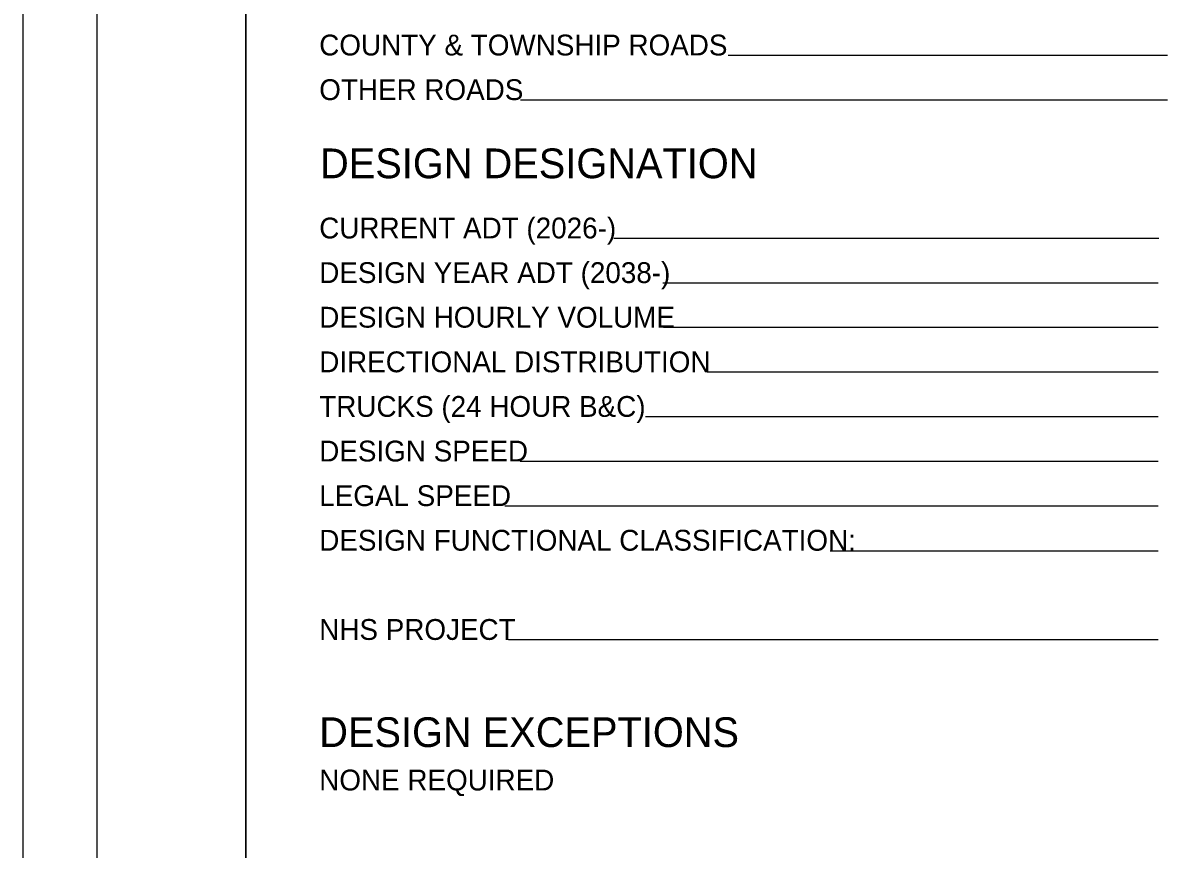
# Model space of a CAD drawing. Extents: x -107 to 120, y -81 to 213.
# Drawn here: x 3.89 to 11.53, y 7.13 to 12.69 of the extents above; entities that cross this region are included whole.
import ezdxf

# ---------------------------------------------------------------- set-up
doc = ezdxf.new("R2010")
doc.units = 0
for name, color, linetype in [('SH_Border', 7, 'Continuous'), ('SH_Cut_Line', 7, 'Continuous'), ('SH_Data', 7, 'Continuous'), ('SH_Text', 7, 'Continuous')]:
    doc.layers.add(name, color=color, linetype=linetype)

msp = doc.modelspace()

# ---------------------------------------------------------------- linework, layer by layer
at = {"layer": 'SH_Border'}
for points in [[(4.389, 23.0682), (5.389, 23.0682), (5.389, 2.0682), (4.389, 2.0682)], [(5.389, 23.0682), (37.389, 23.0682), (37.389, 2.0682), (5.389, 2.0682)]]:
    msp.add_lwpolyline(points, close=True, dxfattribs=at)
at = {"layer": 'SH_Cut_Line'}
msp.add_lwpolyline([(3.889, 1.5682), (37.889, 1.5682), (37.889, 23.5682), (3.889, 23.5682)], close=True, dxfattribs=at)
at = {"layer": 'SH_Data'}
for p, q in [((11.589, 12.4657), (8.6342, 12.4657)), ((11.589, 12.1657), (7.2361, 12.1657)), ((11.5314, 11.2351), (7.8657, 11.2351)), ((11.5258, 10.9351), (8.1935, 10.9351)), ((11.5258, 10.6351), (8.1992, 10.6351)), ((11.5258, 10.3351), (8.4927, 10.3351)), ((11.5258, 10.0351), (8.0775, 10.0351)), ((11.5258, 9.7351), (7.2349, 9.7351)), ((11.5258, 9.4351), (7.1312, 9.4351)), ((11.5258, 9.1313), (9.3191, 9.1313)), ((11.5258, 8.5351), (7.1559, 8.5351))]:
    msp.add_line(p, q, dxfattribs=at)

# ---------------------------------------------------------------- texts
msp.add_text('DESIGN DESIGNATION', height=0.2, dxfattribs=at).set_placement((5.889, 11.64))
at = {"layer": 'SH_Text'}
for s, height, p in [('COUNTY & TOWNSHIP ROADS', 0.14, (5.8834, 12.4657)), ('OTHER ROADS', 0.14, (5.8834, 12.1657)), ('CURRENT ADT (2026-)', 0.14, (5.8834, 11.2351)), ('DESIGN YEAR ADT (2038-)', 0.14, (5.8834, 10.9351)), ('DESIGN HOURLY VOLUME', 0.14, (5.8834, 10.6351)), ('DIRECTIONAL DISTRIBUTION', 0.14, (5.8834, 10.3351)), ('TRUCKS (24 HOUR B&C)', 0.14, (5.8834, 10.0351)), ('DESIGN SPEED', 0.14, (5.8834, 9.7351)), ('LEGAL SPEED', 0.14, (5.8834, 9.4351)), ('DESIGN FUNCTIONAL CLASSIFICATION:', 0.14, (5.8834, 9.1351)), ('NHS PROJECT', 0.14, (5.8834, 8.5351)), ('DESIGN EXCEPTIONS', 0.2, (5.8834, 7.8145)), ('NONE REQUIRED', 0.14, (5.8834, 7.5226))]:
    msp.add_text(s, height=height, dxfattribs=at).set_placement(p)

doc.saveas('drawing.dxf')
